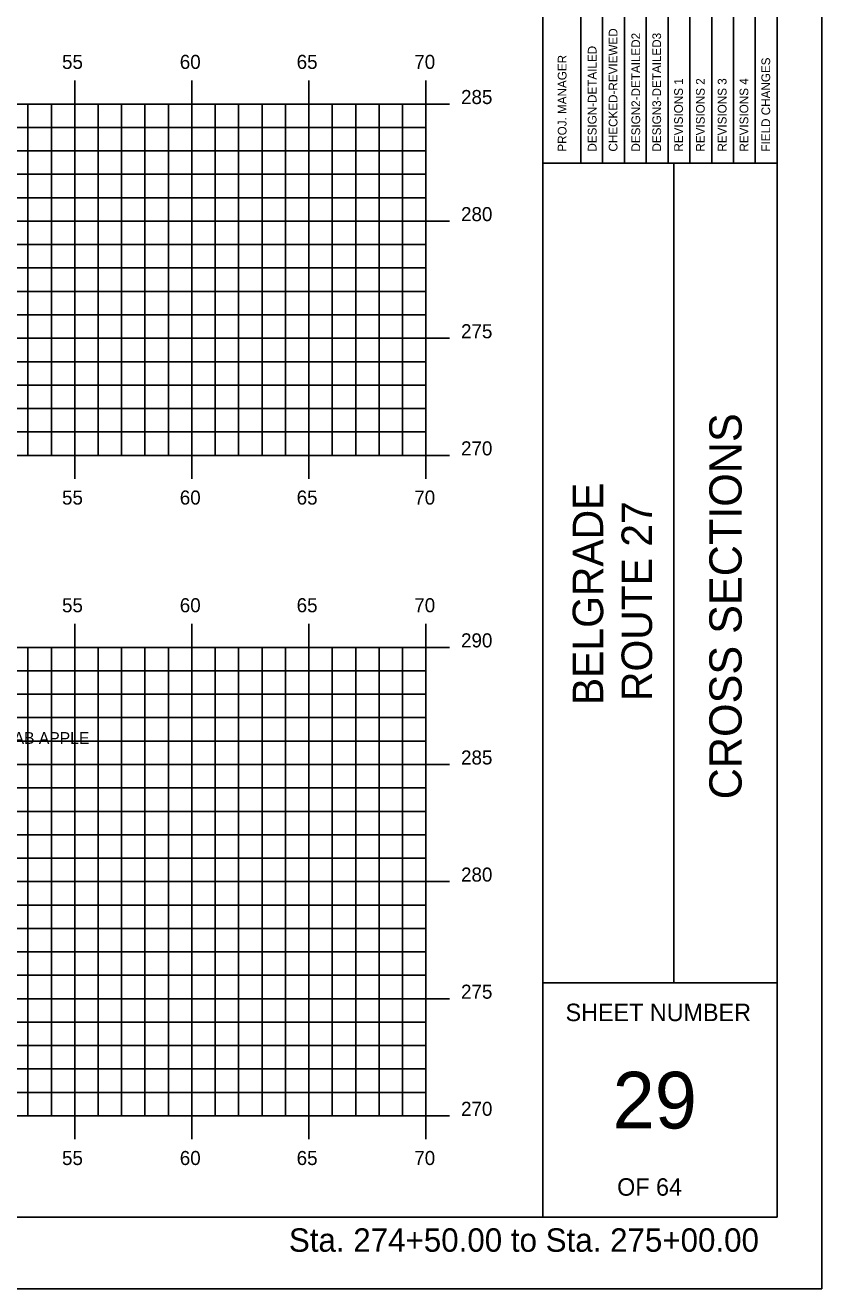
# Model space of a CAD drawing. Extents: x 853340 to 853510, y 366268 to 366378.
# Drawn here: x 853476 to 853510, y 366268.2 to 366322.1 of the extents above; entities that cross this region are included whole.
import ezdxf

# ---------------------------------------------------------------- set-up
doc = ezdxf.new("R2010")
doc.units = 0
for name, color, linetype in [('BORDER', 7, 'Continuous'), ('D_Text_Monospaced', 7, 'Continuous'), ('H_V ANNOTATION', 7, 'Continuous'), ('HIGHWAY_TITLE', 7, 'Continuous'), ('MAJOR', 7, 'Continuous'), ('MINOR', 7, 'Continuous'), ('PLOT BOUNDARY', 7, 'Continuous')]:
    doc.layers.add(name, color=color, linetype=linetype)

msp = doc.modelspace()

# ---------------------------------------------------------------- linework, layer by layer
at = {"layer": 'BORDER'}
for p, q in [((853498.1, 366271.236), (853498.1, 366376.239)), ((853508.1, 366271.236), (853508.1, 366376.236)), ((853498.1, 366316.239), (853508.1, 366316.239)), ((853503.691, 366281.239), (853503.691, 366316.239)), ((853498.1, 366281.239), (853508.1, 366281.239)), ((853348.1, 366271.236), (853508.1, 366271.236))]:
    msp.add_line(p, q, dxfattribs=at)
for points in [[(853500.647, 366316.242), (853500.647, 366333.739)], [(853501.579, 366333.739), (853501.579, 366316.242)], [(853502.511, 366316.242), (853502.511, 366333.739)], [(853503.442, 366316.242), (853503.442, 366333.739)], [(853504.374, 366316.242), (853504.374, 366333.739)], [(853505.306, 366316.242), (853505.306, 366333.739)], [(853506.238, 366316.242), (853506.238, 366333.739)], [(853507.169, 366316.242), (853507.169, 366333.739)], [(853499.716, 366316.242), (853499.716, 366333.033)]]:
    msp.add_lwpolyline(points, dxfattribs=at)
at = {"layer": 'MAJOR'}
for p, q in [((853478.1, 366319.759), (853478.1, 366318.757)), ((853483.1, 366319.759), (853483.1, 366318.757)), ((853488.1, 366319.759), (853488.1, 366318.757)), ((853493.1, 366319.759), (853493.1, 366318.757)), ((853353.1, 366318.757), (853493.1, 366318.757)), ((853353.1, 366318.757), (853493.1, 366318.757)), ((853478.1, 366303.757), (853478.1, 366318.757)), ((853483.1, 366303.757), (853483.1, 366318.757)), ((853488.1, 366303.757), (853488.1, 366318.757)), ((853494.102, 366318.757), (853492.098, 366318.757)), ((853493.1, 366303.757), (853493.1, 366318.757)), ((853493.1, 366303.757), (853493.1, 366318.757)), ((853353.1, 366313.757), (853493.1, 366313.757)), ((853494.102, 366313.757), (853492.098, 366313.757)), ((853353.1, 366308.757), (853493.1, 366308.757)), ((853494.102, 366308.757), (853492.098, 366308.757)), ((853353.1, 366303.757), (853493.1, 366303.757)), ((853478.1, 366302.755), (853478.1, 366303.757)), ((853483.1, 366302.755), (853483.1, 366303.757)), ((853488.1, 366302.755), (853488.1, 366303.757)), ((853494.102, 366303.757), (853492.098, 366303.757)), ((853493.1, 366302.755), (853493.1, 366303.757)), ((853478.1, 366296.561), (853478.1, 366295.559)), ((853483.1, 366296.561), (853483.1, 366295.559)), ((853488.1, 366296.561), (853488.1, 366295.559)), ((853493.1, 366296.561), (853493.1, 366295.559)), ((853353.1, 366295.559), (853493.1, 366295.559)), ((853353.1, 366295.559), (853493.1, 366295.559)), ((853478.1, 366275.559), (853478.1, 366295.559)), ((853483.1, 366275.559), (853483.1, 366295.559)), ((853488.1, 366275.559), (853488.1, 366295.559)), ((853494.102, 366295.559), (853492.098, 366295.559)), ((853493.1, 366275.559), (853493.1, 366295.559)), ((853493.1, 366275.559), (853493.1, 366295.559)), ((853353.1, 366290.559), (853493.1, 366290.559)), ((853494.102, 366290.559), (853492.098, 366290.559)), ((853353.1, 366285.559), (853493.1, 366285.559)), ((853494.102, 366285.559), (853492.098, 366285.559)), ((853353.1, 366280.559), (853493.1, 366280.559)), ((853494.102, 366280.559), (853492.098, 366280.559)), ((853353.1, 366275.559), (853493.1, 366275.559)), ((853353.1, 366275.559), (853493.1, 366275.559)), ((853478.1, 366274.557), (853478.1, 366275.559)), ((853483.1, 366274.557), (853483.1, 366275.559)), ((853488.1, 366274.557), (853488.1, 366275.559)), ((853494.102, 366275.559), (853492.098, 366275.559)), ((853493.1, 366274.557), (853493.1, 366275.559))]:
    msp.add_line(p, q, dxfattribs=at)
at = {"layer": 'MINOR'}
for p, q in [((853476.1, 366303.757), (853476.1, 366318.757)), ((853477.1, 366303.757), (853477.1, 366318.757)), ((853479.1, 366303.757), (853479.1, 366318.757)), ((853480.1, 366303.757), (853480.1, 366318.757)), ((853481.1, 366303.757), (853481.1, 366318.757)), ((853482.1, 366303.757), (853482.1, 366318.757)), ((853484.1, 366303.757), (853484.1, 366318.757)), ((853485.1, 366303.757), (853485.1, 366318.757)), ((853486.1, 366303.757), (853486.1, 366318.757)), ((853487.1, 366303.757), (853487.1, 366318.757)), ((853489.1, 366303.757), (853489.1, 366318.757)), ((853490.1, 366303.757), (853490.1, 366318.757)), ((853491.1, 366303.757), (853491.1, 366318.757)), ((853492.1, 366303.757), (853492.1, 366318.757)), ((853353.1, 366317.757), (853493.1, 366317.757)), ((853493.1, 366317.757), (853492.098, 366317.757)), ((853353.1, 366316.757), (853493.1, 366316.757)), ((853493.1, 366316.757), (853492.098, 366316.757)), ((853353.1, 366315.757), (853493.1, 366315.757)), ((853493.1, 366315.757), (853492.098, 366315.757)), ((853353.1, 366314.757), (853493.1, 366314.757)), ((853493.1, 366314.757), (853492.098, 366314.757)), ((853353.1, 366312.757), (853493.1, 366312.757)), ((853493.1, 366312.757), (853492.098, 366312.757)), ((853353.1, 366311.757), (853493.1, 366311.757)), ((853493.1, 366311.757), (853492.098, 366311.757)), ((853353.1, 366310.757), (853493.1, 366310.757)), ((853493.1, 366310.757), (853492.098, 366310.757)), ((853353.1, 366309.757), (853493.1, 366309.757)), ((853493.1, 366309.757), (853492.098, 366309.757)), ((853353.1, 366307.757), (853493.1, 366307.757)), ((853493.1, 366307.757), (853492.098, 366307.757)), ((853353.1, 366306.757), (853493.1, 366306.757)), ((853493.1, 366306.757), (853492.098, 366306.757)), ((853353.1, 366305.757), (853493.1, 366305.757)), ((853493.1, 366305.757), (853492.098, 366305.757)), ((853353.1, 366304.757), (853493.1, 366304.757)), ((853493.1, 366304.757), (853492.098, 366304.757)), ((853476.1, 366275.559), (853476.1, 366295.559)), ((853477.1, 366275.559), (853477.1, 366295.559)), ((853479.1, 366275.559), (853479.1, 366295.559)), ((853480.1, 366275.559), (853480.1, 366295.559)), ((853481.1, 366275.559), (853481.1, 366295.559)), ((853482.1, 366275.559), (853482.1, 366295.559)), ((853484.1, 366275.559), (853484.1, 366295.559)), ((853485.1, 366275.559), (853485.1, 366295.559)), ((853486.1, 366275.559), (853486.1, 366295.559)), ((853487.1, 366275.559), (853487.1, 366295.559)), ((853489.1, 366275.559), (853489.1, 366295.559)), ((853490.1, 366275.559), (853490.1, 366295.559)), ((853491.1, 366275.559), (853491.1, 366295.559)), ((853492.1, 366275.559), (853492.1, 366295.559)), ((853353.1, 366294.559), (853493.1, 366294.559)), ((853493.1, 366294.559), (853492.098, 366294.559)), ((853353.1, 366293.559), (853493.1, 366293.559)), ((853493.1, 366293.559), (853492.098, 366293.559)), ((853353.1, 366292.559), (853493.1, 366292.559)), ((853493.1, 366292.559), (853492.098, 366292.559)), ((853353.1, 366291.559), (853493.1, 366291.559)), ((853493.1, 366291.559), (853492.098, 366291.559)), ((853353.1, 366289.559), (853493.1, 366289.559)), ((853493.1, 366289.559), (853492.098, 366289.559)), ((853353.1, 366288.559), (853493.1, 366288.559)), ((853493.1, 366288.559), (853492.098, 366288.559)), ((853353.1, 366287.559), (853493.1, 366287.559)), ((853493.1, 366287.559), (853492.098, 366287.559)), ((853353.1, 366286.559), (853493.1, 366286.559)), ((853493.1, 366286.559), (853492.098, 366286.559)), ((853353.1, 366284.559), (853493.1, 366284.559)), ((853493.1, 366284.559), (853492.098, 366284.559)), ((853353.1, 366283.559), (853493.1, 366283.559)), ((853493.1, 366283.559), (853492.098, 366283.559)), ((853353.1, 366282.559), (853493.1, 366282.559)), ((853493.1, 366282.559), (853492.098, 366282.559)), ((853353.1, 366281.559), (853493.1, 366281.559)), ((853493.1, 366281.559), (853492.098, 366281.559)), ((853353.1, 366279.559), (853493.1, 366279.559)), ((853493.1, 366279.559), (853492.098, 366279.559)), ((853353.1, 366278.559), (853493.1, 366278.559)), ((853493.1, 366278.559), (853492.098, 366278.559)), ((853353.1, 366277.559), (853493.1, 366277.559)), ((853493.1, 366277.559), (853492.098, 366277.559)), ((853353.1, 366276.559), (853493.1, 366276.559)), ((853493.1, 366276.559), (853492.098, 366276.559))]:
    msp.add_line(p, q, dxfattribs=at)
at = {"layer": 'PLOT BOUNDARY'}
msp.add_lwpolyline([(853340.007, 366268.177), (853510.007, 366268.177), (853510.007, 366378.177), (853340.007, 366378.177)], close=True, dxfattribs=at)

# ---------------------------------------------------------------- texts
at = {"layer": 'BORDER'}
for s, height, rotation, p in [('CHECKED-REVIEWED', 0.37275, 90, (853501.281, 366316.727)), ('DESIGN2-DETAILED2', 0.37275, 90, (853502.25, 366316.727)), ('DESIGN3-DETAILED3', 0.37275, 90, (853503.144, 366316.727)), ('DESIGN-DETAILED', 0.37275, 90, (853500.387, 366316.727)), ('PROJ. MANAGER', 0.37275, 90, (853499.104, 366316.727)), ('FIELD CHANGES', 0.37275, 90, (853507.803, 366316.727)), ('REVISIONS 1', 0.37275, 90, (853504.076, 366316.727)), ('REVISIONS 2', 0.37275, 90, (853505.008, 366316.727)), ('REVISIONS 3', 0.37275, 90, (853505.939, 366316.727)), ('REVISIONS 4', 0.37275, 90, (853506.871, 366316.727)), ('CROSS SECTIONS', 1.37787, 90, (853506.584, 366289.073)), ('SHEET NUMBER', 0.74527, 360, (853499.065, 366279.603)), ('29', 2.4194, 360, (853501.076, 366275.019)), ('OF 64', 0.7453, 360, (853501.267, 366272.149))]:
    msp.add_text(s, height=height, rotation=rotation, dxfattribs=at).set_placement(p)
at = {"layer": 'D_Text_Monospaced'}
msp.add_text('EXIST. 12" CRAB APPLE', height=0.49998, dxfattribs=at).set_placement((853471.053, 366291.441))
at = {"layer": 'H_V ANNOTATION'}
for s, height, p in [('55', 0.6, (853477.556, 366320.257)), ('60', 0.6, (853482.586, 366320.257)), ('65', 0.6, (853487.578, 366320.257)), ('70', 0.6, (853492.602, 366320.257)), ('285', 0.6, (853494.6, 366318.757)), ('280', 0.6, (853494.6, 366313.757)), ('275', 0.6, (853494.6, 366308.757)), ('270', 0.6, (853494.6, 366303.757)), ('55', 0.6, (853477.556, 366301.657)), ('60', 0.6, (853482.586, 366301.657)), ('65', 0.6, (853487.578, 366301.657)), ('70', 0.6, (853492.602, 366301.657)), ('55', 0.6, (853477.556, 366297.059)), ('60', 0.6, (853482.586, 366297.059)), ('65', 0.6, (853487.578, 366297.059)), ('70', 0.6, (853492.602, 366297.059)), ('290', 0.6, (853494.6, 366295.559)), ('285', 0.6, (853494.6, 366290.559)), ('280', 0.6, (853494.6, 366285.559)), ('275', 0.6, (853494.6, 366280.559)), ('270', 0.6, (853494.6, 366275.559)), ('55', 0.6, (853477.556, 366273.459)), ('60', 0.6, (853482.586, 366273.459)), ('65', 0.6, (853487.578, 366273.459)), ('70', 0.6, (853492.602, 366273.459)), ('Sta. 274+50.00 to Sta. 275+00.00', 1.0002, (853487.246, 366269.756))]:
    msp.add_text(s, height=height, dxfattribs=at).set_placement(p)
at = {"layer": 'HIGHWAY_TITLE'}
for s, p in [('BELGRADE', (853500.672, 366293.095)), ('ROUTE 27', (853502.759, 366293.269))]:
    msp.add_text(s, height=1.3043, rotation=90, dxfattribs=at).set_placement(p)

doc.saveas('drawing.dxf')
